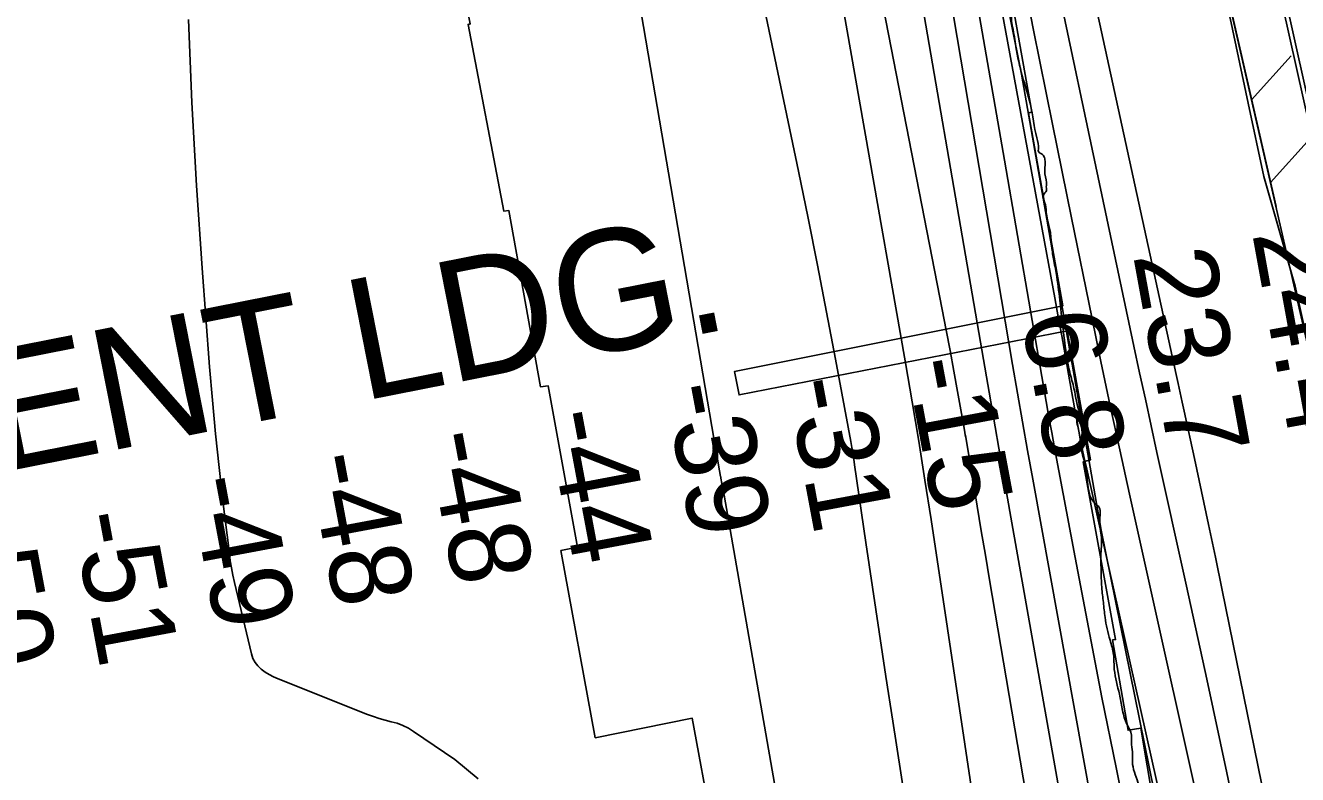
# Model space of a CAD drawing. Extents: x 3419139 to 3457078, y 540382 to 565875.
# Drawn here: x 3439284 to 3440334, y 551203 to 551821 of the extents above; entities that cross this region are included whole.
import ezdxf

# ---------------------------------------------------------------- set-up
doc = ezdxf.new("R2010")
doc.units = 0
for name, color, linetype in [('V-FLOD-BASE', 7, 'Continuous'), ('V-LEVE-TOET', 7, 'Continuous'), ('V-RIVR-EDGE', 7, 'Continuous'), ('V-RIVR-RANG', 7, 'Continuous'), ('V-RRAP-FSHR', 7, 'Continuous'), ('V-RRAP-RVMT', 7, 'Continuous'), ('V-SURV-LINE', 7, 'Continuous'), ('V-TOPO-DPTH', 7, 'Continuous'), ('V-TOPO-GNAM-IDEN', 7, 'Continuous'), ('V-TOPO-MAJR', 7, 'Continuous'), ('V-TOPO-MINR', 7, 'Continuous'), ('V-TOPO-WATR', 7, 'Continuous')]:
    doc.layers.add(name, color=color, linetype=linetype)

msp = doc.modelspace()

# ---------------------------------------------------------------- linework, layer by layer
at = {"layer": 'V-FLOD-BASE'}
msp.add_lwpolyline([(3440043.2, 553091.6), (3440059.9, 553007.1), (3440087.4, 552902.3), (3440113, 552778.5), (3440141.9, 552659.9), (3440163.5, 552562.5), (3440182.4, 552470.3), (3440208, 552356), (3440229.9, 552263.3), (3440247.7, 552177.9), (3440275.5, 552056), (3440300.5, 551951), (3440322.5, 551851.8), (3440341.1, 551767.6), (3440361.6, 551677.7), (3440384.4, 551584.4), (3440400, 551514.2), (3440412.8, 551457.5), (3440426.1, 551391.2), (3440438.9, 551339), (3440453.6, 551276.9), (3440457.5, 551259.7)], dxfattribs=at)
at = {"layer": 'V-LEVE-TOET'}
msp.add_lwpolyline([(3440395.7, 551317.5), (3440385.5, 551375.7), (3440369.1, 551439.4), (3440351.4, 551520.9), (3440332.3, 551605.9), (3440306.4, 551696.4), (3440293.7, 551756.9), (3440278.7, 551827), (3440257.1, 551913.1), (3440241.8, 551985.9), (3440219.9, 552072.6), (3440202.4, 552149.6), (3440183.1, 552253.1), (3440161.2, 552352.3), (3440140.4, 552460.2), (3440117.7, 552556.3), (3440099.9, 552634.8), (3440078.9, 552735.7), (3440058.9, 552826.8), (3440037.8, 552918.2), (3440016.5, 553008.1), (3439996.8, 553101.5)], dxfattribs=at)
at = {"layer": 'V-RIVR-EDGE'}
for points in [[(3440142.2, 551559.1), (3440138.4, 551591.5), (3440135.6, 551613.4), (3440133.2, 551626.8), (3440131.4, 551638.4), (3440130.8, 551646.1), (3440130.1, 551651.4), (3440129, 551656), (3440126.9, 551665.2), (3440126.2, 551672.9), (3440124.5, 551681), (3440127, 551684.6), (3440127, 551686.7), (3440127, 551691.3), (3440125.6, 551700.8), (3440126, 551707.1), (3440125.6, 551711), (3440123.9, 551714.5), (3440120.4, 551717), (3440120.4, 551718.8), (3440119, 551728.3), (3440113.8, 551755.8), (3440107.1, 551779.4), (3440101.9, 551803.4), (3440099.1, 551819.6), (3440098.1, 551825.9), (3440098.8, 551835.1), (3440097.4, 551840.4), (3440092.2, 551859.4), (3440088, 551874.2), (3440079.3, 551918.7), (3440073, 551951.4), (3440067.1, 551985.6), (3440062.9, 552008.9), (3440057.7, 552031.1), (3440056, 552039.2), (3440055.6, 552043.8), (3440055.3, 552047.3), (3440054.2, 552052.6), (3440053.2, 552059.3), (3440050.4, 552068.8), (3440046.2, 552090.3), (3440043.1, 552103.7), (3440033.3, 552131.6), (3440030.1, 552144.7), (3440027.4, 552160.5), (3440024.9, 552173.6)], [(3440606.5, 548542), (3440606.2, 548567.3), (3440602.8, 548588.8), (3440599.6, 548602.9), (3440598.6, 548615.3), (3440596.9, 548630.4), (3440593.4, 548648.4), (3440585, 548681.9), (3440580.8, 548696.7), (3440577.3, 548705.2), (3440573.8, 548711.9), (3440574.2, 548719.3), (3440574.9, 548725.6), (3440572.5, 548739), (3440569.7, 548758.4), (3440569.8, 548774.6), (3440568.4, 548805.6), (3440568.5, 548828.2), (3440566.4, 548832.8), (3440561.1, 548843), (3440560.8, 548848.3), (3440560.8, 548854.6), (3440560.5, 548859.6), (3440561.9, 548864.1), (3440565.4, 548871.5), (3440566.5, 548880.3), (3440566.2, 548891.3), (3440563.4, 548894.8), (3440561.3, 548896.9), (3440560.6, 548898.3), (3440558.8, 548902.2), (3440558.5, 548910.7), (3440559.2, 548920.9), (3440561.7, 548937.1), (3440562.4, 548945.5), (3440562.4, 548952.6), (3440561.8, 548959.3), (3440559.7, 548969.1), (3440557.6, 548979), (3440555.5, 548989.9), (3440553, 548999.8), (3440549.9, 549013.6), (3440549.9, 549021.7), (3440550, 549031.9), (3440548.9, 549037.9), (3440547.2, 549043.2), (3440545.1, 549050.9), (3440542.7, 549081.6), (3440541.7, 549102.7), (3440541.4, 549115.8), (3440539.6, 549121.4), (3440538.2, 549126.4), (3440533.7, 549164.8), (3440530.3, 549193.7), (3440527.5, 549221.9), (3440525.8, 549236), (3440521.2, 549247.6), (3440520.9, 549255.4), (3440519.2, 549278.3), (3440518.5, 549290.3), (3440515.4, 549308.2), (3440514.4, 549315.3), (3440513.7, 549332.9), (3440512.7, 549345.6), (3440510.6, 549348.8), (3440510.6, 549351.9), (3440510.6, 549355.5), (3440510.9, 549359), (3440510.2, 549361.5), (3440507.1, 549368.5), (3440511, 549374.1), (3440511.3, 549378.4), (3440511, 549384), (3440507.9, 549405.9), (3440505.1, 549431.6), (3440503.1, 549458.4), (3440503.2, 549487.3), (3440501.4, 549504.5), (3440495.9, 549538.4), (3440492.1, 549561), (3440488.2, 549573.3), (3440484, 549584.9), (3440480.9, 549598.7), (3440479.9, 549608.6), (3440479.5, 549619.1), (3440476.7, 549636.4), (3440475, 549654.4), (3440466, 549699.9), (3440462.2, 549718.9), (3440459.4, 549740.7), (3440458, 549745.3), (3440454.6, 549780.2), (3440451.1, 549806), (3440446.6, 549857.1), (3440441.5, 549900.4), (3440437, 549938.1), (3440435.9, 549948.7), (3440428.7, 549999.8), (3440424.8, 550021.7), (3440423.5, 550042.1), (3440422.2, 550073.5), (3440419.1, 550101), (3440415.2, 550128.5), (3440409, 550157.7), (3440408, 550174.3), (3440409.4, 550193.7), (3440408.7, 550210.2), (3440405.6, 550227.2), (3440403.9, 550234.9), (3440395.8, 550244.4), (3440387, 550251.5), (3440378.6, 550256.1), (3440372.9, 550264.2), (3440367, 550279), (3440361.8, 550306.2), (3440354.8, 550346), (3440348.9, 550377.8), (3440347.9, 550389.7), (3440349, 550403.1), (3440352.5, 550418.3), (3440352.5, 550423.6), (3440351.1, 550427.4), (3440341.7, 550443), (3440332.5, 550450), (3440330.1, 550453.6), (3440325.2, 550467), (3440324.2, 550488.8), (3440325.3, 550503.3), (3440325.7, 550521.2), (3440325, 550535.3), (3440320.4, 550554.4), (3440313.8, 550578.3), (3440311.7, 550592.1), (3440311.8, 550613.2), (3440308, 550646.7), (3440307.7, 550672.1), (3440307.7, 550684.4), (3440304.2, 550695.4), (3440300.4, 550703.8), (3440296.5, 550714.4), (3440295.5, 550723.9), (3440295.9, 550738.4), (3440295.9, 550747.5), (3440291.4, 550757.4), (3440287.5, 550775.4), (3440284.4, 550791.6), (3440282.7, 550806.4), (3440279.9, 550812.8), (3440279.9, 550816.6), (3440276.7, 550830.7), (3440272.2, 550850.1), (3440262.8, 550882.2), (3440257.2, 550910.8), (3440255.5, 550936.2), (3440255.5, 550947.8), (3440257.7, 550957.3), (3440260.5, 550966.1), (3440264.4, 550979.8), (3440264.1, 550991.1), (3440262, 551009.8), (3440258.5, 551023.5), (3440256.4, 551033.4), (3440256.5, 551038.7), (3440260.7, 551046.4), (3440260.7, 551055.2), (3440257.2, 551067.9), (3440250.9, 551083.8), (3440245.7, 551098.3), (3440234.1, 551119.4), (3440230.2, 551127.6), (3440228.1, 551132.5), (3440221.5, 551140.3), (3440218.3, 551147), (3440212.4, 551159.7), (3440202.6, 551196.3), (3440198, 551213.3), (3440198.1, 551219.3), (3440197.4, 551227.4), (3440196.7, 551237.6), (3440192.8, 551245.7), (3440189.7, 551257), (3440187.3, 551269), (3440183.1, 551289.4), (3440182.4, 551301.7), (3440179.6, 551313.7), (3440175.4, 551332.4), (3440174.1, 551344.8), (3440172.7, 551357.1), (3440172.3, 551367.7), (3440172, 551383.2), (3440172.4, 551398.3), (3440171.1, 551413.5), (3440170, 551424.1), (3440167.9, 551425.8), (3440162.6, 551434.3), (3440159.9, 551454.4), (3440156, 551470.6), (3440152.9, 551490.3), (3440152.9, 551495.3), (3440155.8, 551496.3), (3440155.4, 551498.8), (3440149.8, 551521.4), (3440146.3, 551534.8), (3440142.2, 551559.1)]]:
    msp.add_spline(points, degree=3, dxfattribs=at)
at = {"layer": 'V-RRAP-FSHR'}
for p, q in [((3440296.4, 551759.7), (3440329.1, 551795.9)), ((3440312, 551691.4), (3440344.7, 551727.7))]:
    msp.add_line(p, q, dxfattribs=at)
for points in [[(3439977.8, 552420.6), (3440106.4, 551780.9), (3440172.3, 551404.3), (3440232, 551110), (3440392.8, 550607.1), (3440489.2, 549894.4), (3440511.6, 549607.3), (3440513.8, 549359.3), (3440532, 548929.5), (3440619.8, 548305.6), (3440691.1, 548058.6), (3440757.3, 547660.9), (3440767.5, 547537.4), (3440783.9, 547406), (3441072.2, 545849.7)], [(3440394.3, 551331.8), (3440155.8, 552373.8)], [(3440171.3, 552306.3), (3440316.6, 551671.5)]]:
    msp.add_lwpolyline(points, dxfattribs=at)
at = {"layer": 'V-RRAP-RVMT'}
for points in [[(3439987.6, 552341.4), (3439989.8, 552341.6), (3440016.3, 552197), (3440021.9, 552197.4), (3440049.2, 552051), (3440057.3, 552052.2), (3440083.7, 551906.4), (3440086.9, 551907.1), (3440115.1, 551749.6), (3440112.3, 551748.7), (3440140.5, 551589.5), (3439869.6, 551535.5), (3439873.3, 551516.1), (3440144.3, 551568.9), (3440163.3, 551462.4), (3440157.4, 551460.8), (3440184.1, 551314.1), (3440181.7, 551313.8), (3440194.4, 551239.3), (3440204.9, 551240.9), (3440226.1, 551115.1)], [(3439850.8, 551161.3), (3439834.7, 551249.1), (3439754.6, 551233.1), (3439726.3, 551387.5), (3439740.1, 551390.5), (3439715.8, 551523.5), (3439709.5, 551522.7), (3439683.4, 551668.2), (3439679.3, 551667.6), (3439649.6, 551821.8), (3439651.4, 551822.2), (3439623.8, 551957.8), (3439620.7, 551957.1), (3439594.2, 552097.4), (3439590.1, 552096.3), (3439561.2, 552251.4), (3439584.8, 552256.8)]]:
    msp.add_lwpolyline(points, dxfattribs=at)
at = {"layer": 'V-SURV-LINE'}
msp.add_lwpolyline([(3440547.2, 550829), (3439984.3, 553348.8)], dxfattribs=at)
at = {"layer": 'V-TOPO-DPTH'}
for points in [[(3440073.2, 551137.8), (3440031.8, 551413.3), (3440026.8, 551445.6), (3440021.7, 551477.9), (3440016.3, 551510.2), (3440010.8, 551542.5), (3439943.1, 551928), (3439929.7, 552003), (3439916, 552077.9), (3439901.9, 552152.7), (3439887.5, 552227.5), (3439860.3, 552365.9), (3439859.2, 552371.4), (3439858.1, 552376.9), (3439857, 552382.4), (3439855.9, 552387.9), (3439846, 552436.6), (3439840, 552466.5), (3439833.9, 552496.4), (3439827.9, 552526.2), (3439821.9, 552556.1), (3439680.3, 553262.3)], [(3439680.3, 553262.3), (3439821.9, 552556.1), (3439827.9, 552526.2), (3439833.9, 552496.4), (3439840, 552466.5), (3439846, 552436.6), (3439855.9, 552387.9), (3439857, 552382.4), (3439858.1, 552376.9), (3439859.2, 552371.4), (3439860.3, 552365.9), (3439887.5, 552227.5), (3439901.9, 552152.7), (3439916, 552077.9), (3439929.7, 552003), (3439943.1, 551928), (3440010.8, 551542.5), (3440016.3, 551510.2), (3440021.7, 551477.9), (3440026.8, 551445.6), (3440031.8, 551413.3), (3440073.2, 551137.8)], [(3439858.6, 553097.4), (3439877.8, 553008.5), (3439896.6, 552919.4), (3439915.2, 552830.4), (3439991.4, 552461.5), (3439997.2, 552432.7), (3440003, 552403.9), (3440008.7, 552375), (3440014.3, 552346.2), (3440086.2, 551972.5), (3440101.3, 551894.9), (3440116.5, 551817.2), (3440132, 551739.6), (3440147.7, 551662.1), (3440164.4, 551580.1), (3440172, 551543.6), (3440179.7, 551507.1), (3440187.6, 551470.7), (3440195.6, 551434.2), (3440268.1, 551108.6)], [(3439761.6, 553078.6), (3439781.1, 552989.8), (3439801.3, 552901.1), (3439821.8, 552812.5), (3439904, 552462), (3439912.4, 552425.3), (3439920.6, 552388.5), (3439928.4, 552351.6), (3439935.9, 552314.7), (3439953, 552229.1), (3439968.6, 552149.2), (3439983.8, 552069.3), (3439998.3, 551989.3), (3440012.4, 551909.2), (3440072.6, 551559.5), (3440078.6, 551524.5), (3440084.7, 551489.6), (3440090.8, 551454.6), (3440096.9, 551419.7), (3440206.9, 550797.7)], [(3439761.6, 553078.6), (3439781.1, 552989.8), (3439801.3, 552901.1), (3439821.8, 552812.5), (3439904, 552462), (3439912.4, 552425.3), (3439920.6, 552388.5), (3439928.4, 552351.6), (3439935.9, 552314.7), (3439953, 552229.1), (3439968.6, 552149.2), (3439983.8, 552069.3), (3439998.3, 551989.3), (3440012.4, 551909.2), (3440072.6, 551559.5), (3440078.6, 551524.5), (3440084.7, 551489.6), (3440090.8, 551454.6), (3440096.9, 551419.7), (3440206.9, 550797.7)], [(3439601.7, 553047.3), (3439611.4, 552979.6), (3439621.3, 552912), (3439697.6, 552393.1), (3439701, 552370.7), (3439704.5, 552348.3), (3439708.1, 552325.9), (3439711.8, 552303.5), (3439852.8, 551478.7), (3439853.7, 551473.5), (3439854.6, 551468.4), (3439855.5, 551463.2), (3439856.4, 551458.1), (3439858.1, 551448.8), (3439858.2, 551448.3), (3439858.4, 551447.2), (3439859.2, 551442.9), (3439860.1, 551438), (3439861, 551433.2), (3439975.6, 550777.6)], [(3439975.6, 550777.6), (3439861, 551433.2), (3439860.1, 551438), (3439859.2, 551442.9), (3439858.4, 551447.2), (3439858.2, 551448.3), (3439858.1, 551448.8), (3439856.4, 551458.1), (3439855.5, 551463.2), (3439854.6, 551468.4), (3439853.7, 551473.5), (3439852.8, 551478.7), (3439711.8, 552303.5), (3439708.1, 552325.9), (3439704.5, 552348.3), (3439701, 552370.7), (3439697.6, 552393.1), (3439621.3, 552912), (3439611.4, 552979.6), (3439601.7, 553047.3)], [(3440075.5, 550761.6), (3440000.3, 551246.8), (3439994.6, 551283.6), (3439989, 551320.4), (3439983.5, 551357.3), (3439978.1, 551394.1), (3439968.7, 551458.2), (3439968, 551463.1), (3439967.2, 551467.9), (3439966.4, 551472.7), (3439965.5, 551477.5), (3439952.9, 551545.6), (3439945.6, 551584.4), (3439938.1, 551623.2), (3439930.3, 551662), (3439922.4, 551700.7), (3439796.9, 552299.8)], [(3440075.5, 550761.6), (3440000.3, 551246.8), (3439994.6, 551283.6), (3439989, 551320.4), (3439983.5, 551357.3), (3439978.1, 551394.1), (3439968.7, 551458.2), (3439968, 551463.1), (3439967.2, 551467.9), (3439966.4, 551472.7), (3439965.5, 551477.5), (3439952.9, 551545.6), (3439945.6, 551584.4), (3439938.1, 551623.2), (3439930.3, 551662), (3439922.4, 551700.7), (3439796.9, 552299.8)], [(3440196.2, 551150.7), (3440184.5, 551208.4), (3440172.9, 551266.2), (3440161.7, 551324), (3440150.7, 551381.9), (3440133.7, 551472.3), (3440131.4, 551485), (3440129.1, 551497.8), (3440126.8, 551510.5), (3440124.6, 551523.2), (3440092.5, 551709.8), (3440074.1, 551815.8), (3440055.5, 551921.8)], [(3440196.2, 551150.7), (3440184.5, 551208.4), (3440172.9, 551266.2), (3440161.7, 551324), (3440150.7, 551381.9), (3440133.7, 551472.3), (3440131.4, 551485), (3440129.1, 551497.8), (3440126.8, 551510.5), (3440124.6, 551523.2), (3440092.5, 551709.8), (3440074.1, 551815.8), (3440055.5, 551921.8)]]:
    msp.add_lwpolyline(points, dxfattribs=at)
at = {"layer": 'V-TOPO-MAJR'}
msp.add_lwpolyline([(3439418.8, 551826), (3439421.5, 551757.4), (3439425.4, 551689), (3439430.1, 551620.6), (3439436.3, 551539.3), (3439438.6, 551511.6), (3439441.2, 551483.8), (3439444.1, 551456.1), (3439447.3, 551428.4), (3439452.6, 551385.2), (3439453.4, 551379.2), (3439454.4, 551373.2), (3439455.6, 551367.2), (3439456.9, 551361.3), (3439470.9, 551302.2), (3439472.1, 551298.5), (3439473.8, 551295.2), (3439476.2, 551292.3), (3439479, 551289.6), (3439482.3, 551287.3), (3439485.6, 551285.2), (3439489.1, 551283.4), (3439492.8, 551281.8), (3439566.6, 551252.3), (3439571.5, 551250.5), (3439576.3, 551248.9), (3439581.2, 551247.5), (3439586.2, 551246.3), (3439591.1, 551245), (3439595.9, 551243.2), (3439600.4, 551241), (3439604.7, 551238.3), (3439638.6, 551215.2), (3439657.9, 551199.2)], dxfattribs=at)
at = {"layer": 'V-TOPO-MINR'}
for points in [[(3440369.5, 550876.9), (3440272.2, 551354.8), (3440266.6, 551382), (3440260.9, 551409.2), (3440255.1, 551436.3), (3440249.2, 551463.5), (3440240.7, 551502.5), (3440239, 551510.1), (3440237.4, 551517.7), (3440235.7, 551525.4), (3440234.1, 551533), (3440046, 552396.9), (3440044.9, 552401.7), (3440044.4, 552404.1), (3440043.9, 552406.5), (3440043.1, 552410.5), (3440042.8, 552411.7), (3440042.8, 552412.1), (3440035.8, 552446.6), (3440032.3, 552464.3), (3440028.9, 552482), (3440025.5, 552499.7), (3440022.2, 552517.4), (3439878, 553304.1)], [(3440073.2, 551137.8), (3440031.8, 551413.3), (3440026.8, 551445.6), (3440021.7, 551477.9), (3440016.3, 551510.2), (3440010.8, 551542.5), (3439943.1, 551928), (3439929.7, 552003), (3439916, 552077.9), (3439901.9, 552152.7), (3439887.5, 552227.5), (3439860.3, 552365.9), (3439859.2, 552371.4), (3439858.1, 552376.9), (3439857, 552382.4), (3439855.9, 552387.9), (3439846, 552436.6), (3439840, 552466.5), (3439833.9, 552496.4), (3439827.9, 552526.2), (3439821.9, 552556.1), (3439680.3, 553262.3)], [(3440292.2, 551126.9), (3440276, 551204.1), (3440259.4, 551281.3), (3440242.6, 551358.3), (3440218.3, 551468.6), (3440213.5, 551490.5), (3440208.7, 551512.5), (3440204, 551534.4), (3440199.3, 551556.3), (3440107.1, 551992.4), (3440092.6, 552061.5), (3440078.3, 552130.6), (3440064.1, 552199.8), (3440050.1, 552269), (3440037.6, 552330.9), (3440029.9, 552369.1), (3440022.1, 552407.4), (3440014.3, 552445.7), (3440006.4, 552483.9), (3439871.9, 553137.2)], [(3440268.1, 551108.6), (3440195.6, 551434.2), (3440187.6, 551470.7), (3440179.7, 551507.1), (3440172, 551543.6), (3440164.4, 551580.1), (3440147.7, 551662.1), (3440132, 551739.6), (3440116.5, 551817.2), (3440101.3, 551894.9), (3440086.2, 551972.5), (3440014.3, 552346.2), (3440008.7, 552375), (3440003, 552403.9), (3439997.2, 552432.7), (3439991.4, 552461.5), (3439915.2, 552830.4), (3439896.6, 552919.4), (3439877.8, 553008.5), (3439858.6, 553097.4)], [(3440206.9, 550797.7), (3440096.9, 551419.7), (3440090.8, 551454.6), (3440084.7, 551489.6), (3440078.6, 551524.5), (3440072.6, 551559.5), (3440012.4, 551909.2), (3439998.3, 551989.3), (3439983.8, 552069.3), (3439968.6, 552149.2), (3439953, 552229.1), (3439935.9, 552314.7), (3439928.4, 552351.6), (3439920.6, 552388.5), (3439912.4, 552425.3), (3439904, 552462), (3439821.8, 552812.5), (3439801.3, 552901.1), (3439781.1, 552989.8), (3439761.6, 553078.6)], [(3439601.7, 553047.3), (3439611.4, 552979.6), (3439621.3, 552912), (3439697.6, 552393.1), (3439701, 552370.7), (3439704.5, 552348.3), (3439708.1, 552325.9), (3439711.8, 552303.5), (3439852.8, 551478.7), (3439853.7, 551473.5), (3439854.6, 551468.4), (3439855.5, 551463.2), (3439856.4, 551458.1), (3439858.1, 551448.8), (3439858.2, 551448.3), (3439858.4, 551447.2), (3439859.2, 551442.9), (3439860.1, 551438), (3439861, 551433.2), (3439975.6, 550777.6)], [(3440222.7, 551176.8), (3440160.3, 551454.8), (3440158.6, 551462.6), (3440156.9, 551470.4), (3440155.3, 551478.2), (3440153.8, 551486.1), (3440151.5, 551498.2), (3440151.1, 551500), (3440150.8, 551501.8), (3440150.2, 551505.4), (3440145.3, 551533.3), (3440142.5, 551549), (3440139.7, 551564.8), (3440136.8, 551580.5), (3440133.9, 551596.3), (3439993.1, 552360.3)], [(3440179.3, 550779.3), (3440080.1, 551363.4), (3440076.7, 551383.7), (3440073.2, 551403.9), (3440069.9, 551424.2), (3440066.5, 551444.4), (3440060.4, 551481.2), (3440060, 551483.1), (3440059.7, 551485), (3440059.1, 551488.7), (3440053.7, 551518.8), (3440050.7, 551535.7), (3440047.6, 551552.7), (3440044.4, 551569.6), (3440041.1, 551586.5), (3439893.5, 552343.3)], [(3440075.5, 550761.6), (3440000.3, 551246.8), (3439994.6, 551283.6), (3439989, 551320.4), (3439983.5, 551357.3), (3439978.1, 551394.1), (3439968.7, 551458.2), (3439968, 551463.1), (3439967.2, 551467.9), (3439966.4, 551472.7), (3439965.5, 551477.5), (3439952.9, 551545.6), (3439945.6, 551584.4), (3439938.1, 551623.2), (3439930.3, 551662), (3439922.4, 551700.7), (3439796.9, 552299.8)], [(3440164.6, 551177.7), (3440115.7, 551446.4), (3440111.5, 551470.1), (3440107.3, 551493.7), (3440103.2, 551517.4), (3440099.1, 551541.1), (3439992.4, 552172.3)]]:
    msp.add_lwpolyline(points, dxfattribs=at)
at = {"layer": 'V-TOPO-WATR'}
msp.add_lwpolyline([(3440196.2, 551150.7), (3440184.5, 551208.4), (3440172.9, 551266.2), (3440161.7, 551324), (3440150.7, 551381.9), (3440133.7, 551472.3), (3440131.4, 551485), (3440129.1, 551497.8), (3440126.8, 551510.5), (3440124.6, 551523.2), (3440092.5, 551709.8), (3440074.1, 551815.8), (3440055.5, 551921.8)], dxfattribs=at)

# ---------------------------------------------------------------- texts
at = {"layer": 'V-RIVR-RANG'}
for s, rotation, p in [('24.4', 280.3183, (3440296.8, 551649.5)), ('23.7', 280.3183, (3440198.5, 551631.4)), ('6.8', 280.3183, (3440106.1, 551580.5)), ('-15', 280.6027, (3440010.9, 551543.2)), ('-39', 280.6027, (3439811.4, 551522.2)), ('-31', 280.6027, (3439912.2, 551526.8)), ('-44', 280.6027, (3439713.7, 551500.4)), ('-48', 280.6027, (3439615.2, 551483)), ('-48', 280.6027, (3439516.9, 551464.8)), ('-49', 280.6027, (3439418.7, 551445.9)), ('-51', 280.6027, (3439322.5, 551416.3)), ('-50', 280.6027, (3439221.5, 551412.7))]:
    msp.add_text(s, height=67, rotation=rotation, dxfattribs=at).set_placement(p)
at = {"layer": 'V-TOPO-GNAM-IDEN'}
msp.add_text('CONVENT LDG.', height=100, rotation=11.1762, dxfattribs=at).set_placement((3438883.7, 551376.8))

doc.saveas('drawing.dxf')
